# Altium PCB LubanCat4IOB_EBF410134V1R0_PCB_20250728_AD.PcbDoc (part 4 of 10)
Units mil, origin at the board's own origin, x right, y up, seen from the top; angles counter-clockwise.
Board outline 5236.21 x 4055.11 mil, 6 copper layers (TOP, GND02, ART03, PWR04, GND05, BOTTOM), stack 47.2 mil thick; 614 components, 490 nets, 2311 pads, 1916 vias.
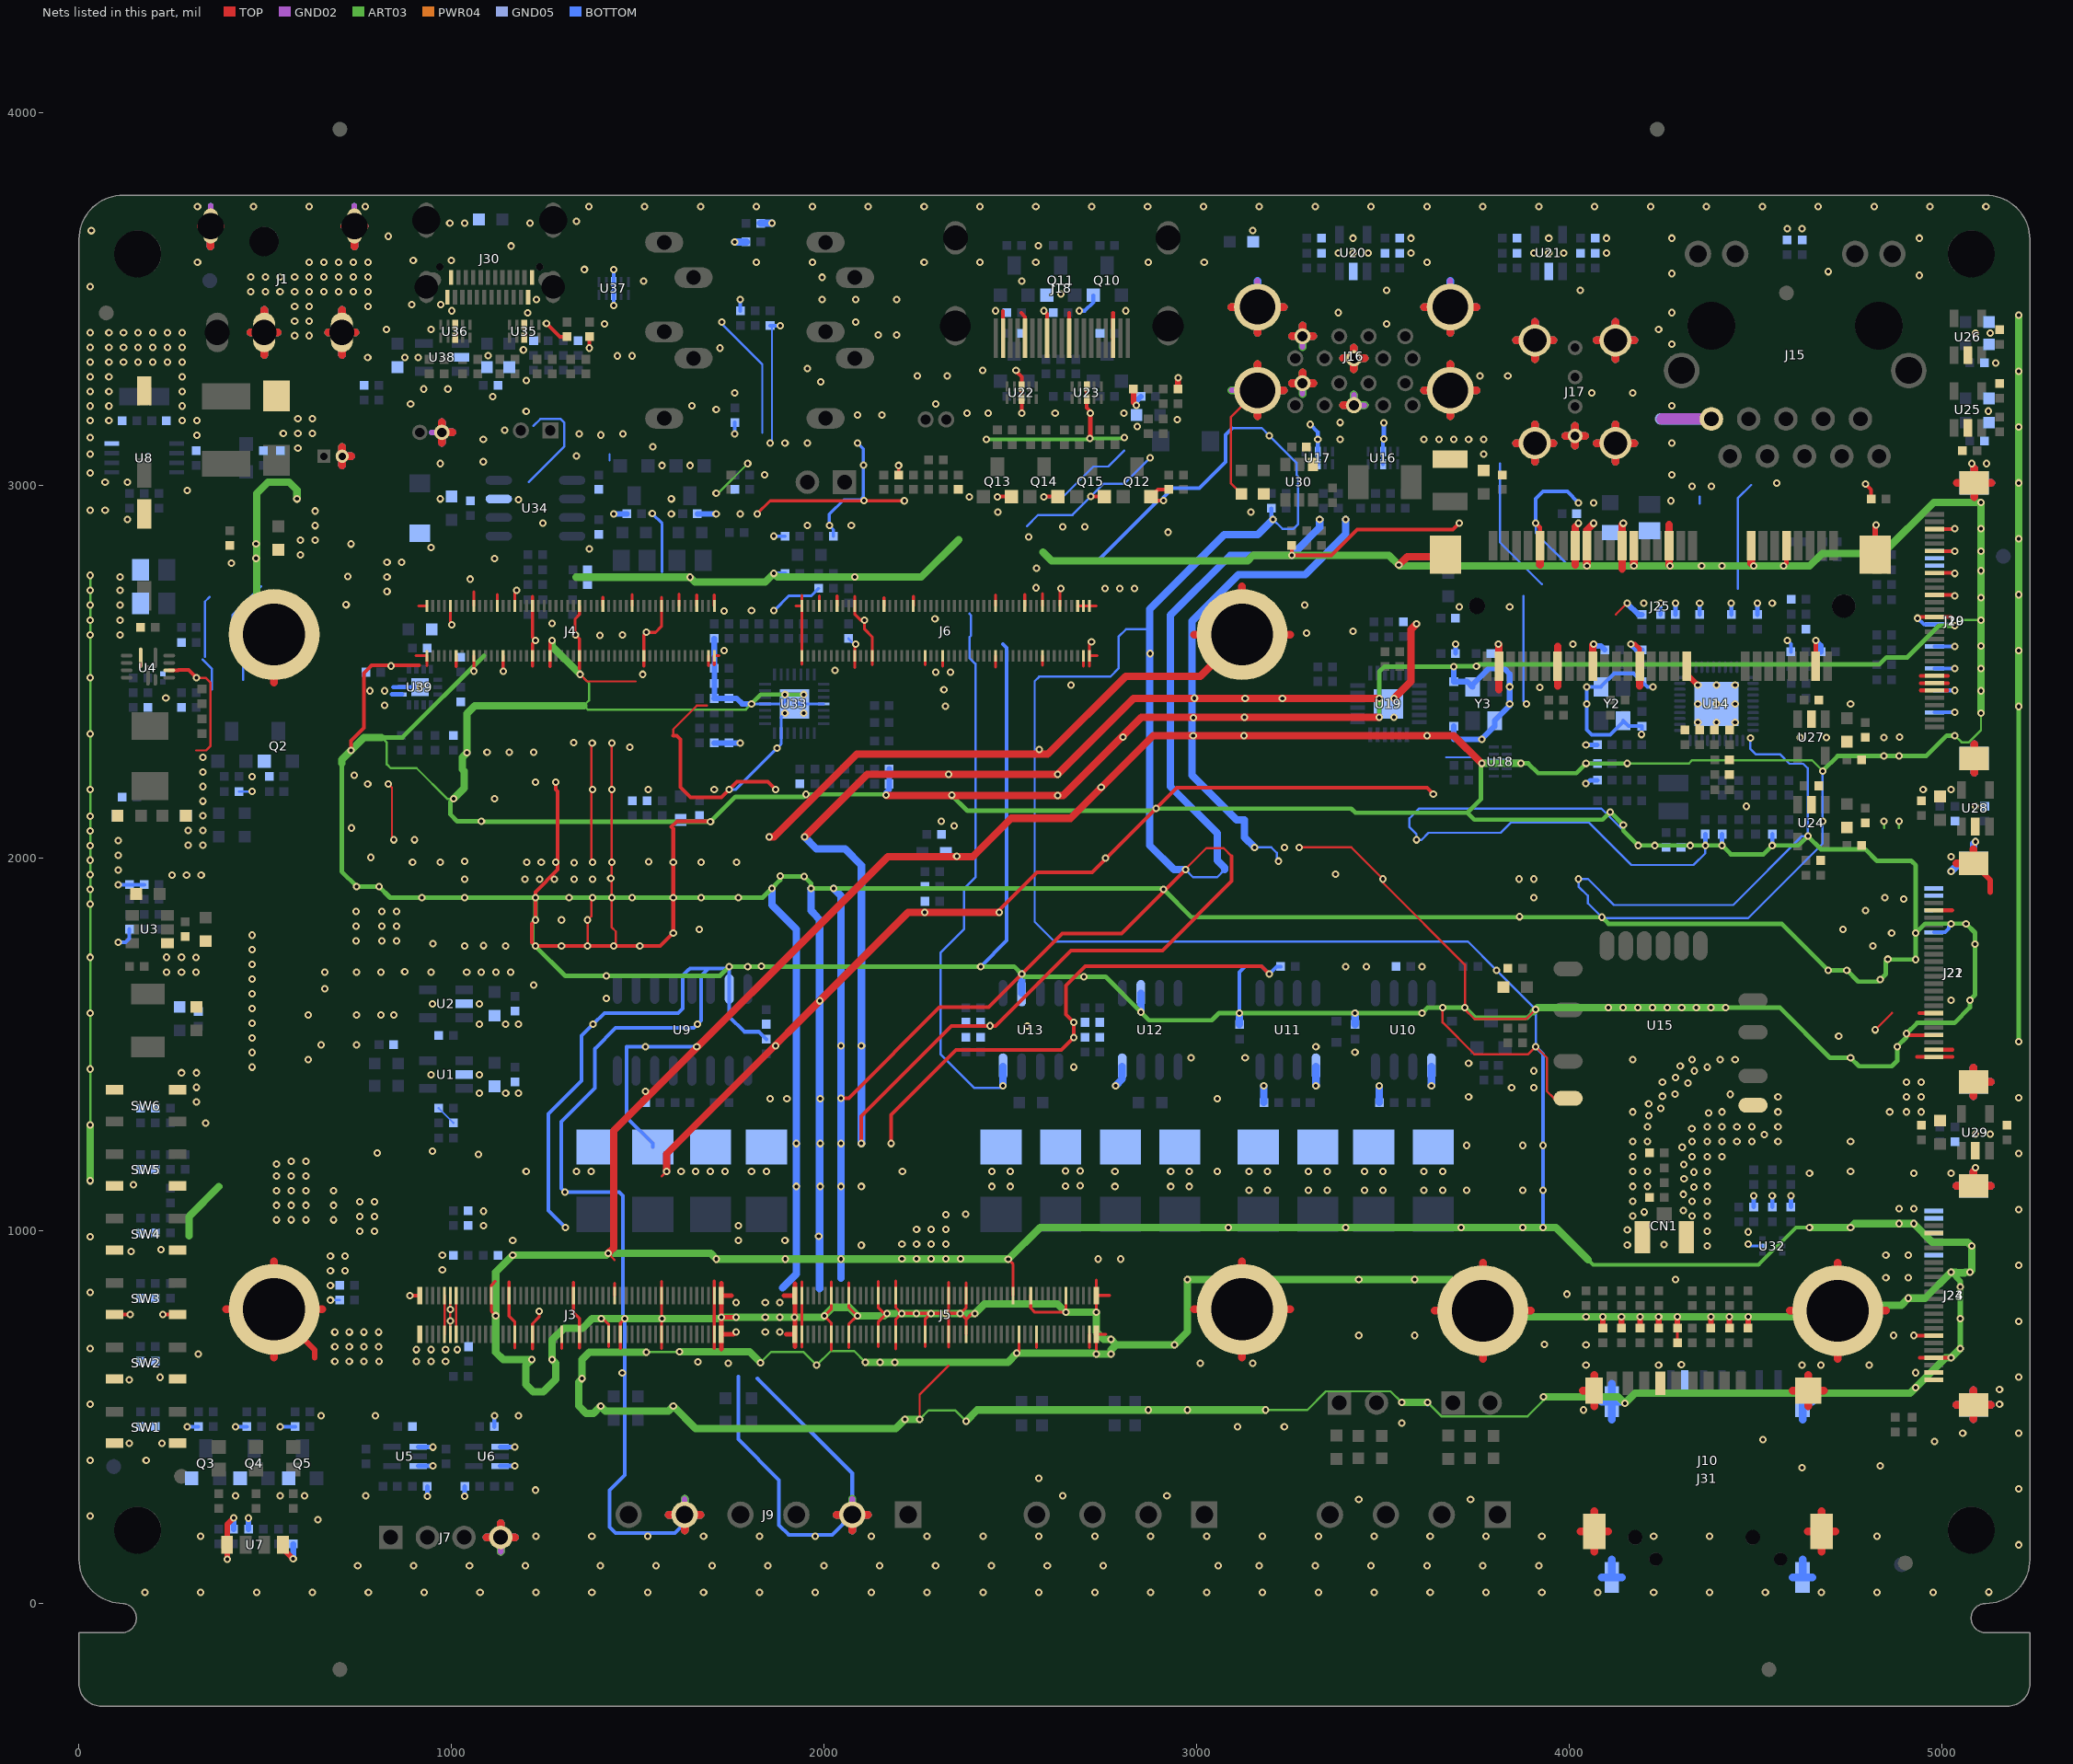
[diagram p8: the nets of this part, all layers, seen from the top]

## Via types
v1: diameter 20, hole 10, TOP to BOTTOM, 1912 vias
v2: diameter 40/50/50/50/50/40 (per signal layer), hole 0, TOP to BOTTOM, 4 vias

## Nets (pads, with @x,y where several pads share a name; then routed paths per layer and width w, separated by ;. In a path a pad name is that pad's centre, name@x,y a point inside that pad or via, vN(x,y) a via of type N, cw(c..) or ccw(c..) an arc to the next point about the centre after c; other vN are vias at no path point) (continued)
GND: C1.2 C2.2 C3.2 C4.2 C5.2 C6.2 C7.2 C8.2 C11.2 C12.2 C13.2 C14.2 C15.2 C16.2 C17.2 C18.1 C19.2 C21.2 C22.2 C23.2 C24.2 C25.2 C26.2 C27.2 C28.2 C29.2 C30.2 C31.2 C32.2 C33.2 C34.2 C35.2 C36.2 C37.2 C38.2 C39.2 C40.2 C41.2 C42.2 C43.2 C44.2 C45.2 C46.2 C47.2 C48.2 C49.2 C50.2 C51.2 C52.2 C53.2 C54.2 C55.2 C58.2 C59.2 C60.2 C61.2 C62.2 C63.2 C64.2 C65.2 C66.2 C67.2 C68.2 C69.2 C70.2 C71.2 C72.2 C73.2 C74.2 C75.2 C76.2 C77.2 C78.2 C79.2 C80.2 C81.2 C82.2 C83.2 C84.2 C85.2 C86.2 C87.2 C88.2 C89.2 C90.2 C92.2 C93.2 C95.2 C96.2 C99.2 C100.2 C101.2 C102.1 C103.2 C104.2 C105.2 C106.2 C107.2 C108.2 C109.2 C110.2 C111.2 C112.2 C124.2 C125.2 C126.2 C127.2 C128.2 C129.2 C130.2 C131.2 C132.2 C133.2 C134.2 C135.2 C136.2 C137.2 C138.2 C139.2 C140.2 C141.2 C142.2 C143.2 C144.2 C147.2 C148.2 C149.2 C150.2 C151.2 C152.2 C153.2 C154.2 C155.2 C158.2 C159.2 C160.2 C161.2 C162.2 C163.2 C164.2 C165.2 C166.2 C167.2 C168.2 C169.2 C170.2 C171.2 C172.2 C173.2 C174.2 C175.2 C180.2 C181.2 C182.2 C183.2 C186.2 C187.2 C188.2 C189.2 C190.2 C192.2 C195.2 C196.2 C203.2 C204.2 C205.2 C206.2 C207.2 C209.2 C210.2 C211.2 C212.2 CN1.2 CN1.3 D1.1 D2.2 D6.1 D7.1 D8.1 D9.1 D10.1 D11.1 D12.1 D13.1 D14.1 D15.1 D16.1 D17.1 D18.1 D20.1 D21.1 D22.1 D24.1 D25.1 D26.1 D27.1 D29.1 D30.1 D31.1 D32.1 D33.1 D34.1 D35.2 D36.2 J1.1 J1.2 J1.3 J1.5 J2.2 J3.7 J3.8 J3.9 J3.10 J3.11 J3.12 J3.23 J3.29 J3.32 J3.38 J3.48 J3.51 J3.54 J3.64 J3.65 J3.68 J3.81 J3.82 J3.99 J3.100 J3.101 J3.102 J3.103 J3.104 J4.1 J4.2 J4.10 J4.11 J4.17 J4.18 J4.26 J4.27 J4.32 J4.37 J4.38 J4.43 J4.53 J4.54 J4.62 J4.72 J4.75 J4.82 J4.88 J4.94 J4.97 J4.99 J4.100 J5.1 J5.2 J5.11 J5.12 J5.17 J5.18 J5.27 J5.28 J5.33 J5.34 J5.44 J5.51 J5.52 J5.57 J5.58 J5.73 J5.76 J5.79 J5.82 J5.91 J5.100 J5.101 J5.102 J5.103 J5.104 J6.1 J6.2 J6.8 J6.14 J6.19 J6.20 J6.25 J6.30 J6.40 J6.43 J6.49 J6.67 J6.68 J6.78 J6.83 J6.84 J6.90 J6.96 J6.97 J6.98 J6.99 J6.100 J7.4 J8.2 J9.2 J9.5 J10.6 J10.10 J10.11 J10.12 J10.13 J15.10 J16.4 J16.7 J16.13 J16.16 J16.19 J16.20 J16.21 J16.22 J17.4 J17.5 J17.6 J17.7 J17.8 J18.2 J18.5 J18.8 J18.11 J18.17 J19.6 J19.7 J19.8 J19.16 J19.19 J19.22 J19.25 J19.28 J19.31 J19.32 J20.6 J20.7 J20.8 J20.16 J20.19 J20.22 J20.25 J20.28 J20.31 J20.32 J21.4 J21.18 J21.21 J21.23 J21.24 J21.25 J21.26 J22.4 J22.18 J22.21 J22.23 J22.24 J22.25 J22.26 J23.4 J23.18 J23.21 J23.23 J23.24 J23.25 J23.26 J24.4 J24.18 J24.21 J24.23 J24.24 J24.25 J24.26 J25.4 J25.9 J25.15 J25.18 J25.21 J25.26 J25.27 J25.29 J25.34 J25.35 J25.37 J25.40 J25.43 J25.50 J25.53 J25.54 J30.A1 J30.A12 J30.B1 J30.B12 J31.5 J31.8 J31.9 J31.10 J31.11 L5.2 L7.2 Q2.2 Q3.2 Q4.2 Q5.2 Q10.2 Q11.2 Q12.2 Q13.2 Q14.2 Q15.2 R4.2 R5.2 R7.2 R9.2 R16.2 R17.1 R20.2 R22.1 R24.2 R40.2 R41.2 R42.2 R64.2 R65.2 R72.2 R73.2 R83.2 R86.2 R91.2 R92.2 R98.2 R99.2 R100.2 R101.2 R102.2 R103.2 R121.2 R125.2 R142.2 R146.2 R157.2 R158.2 R159.2 R160.2 R166.2 R168.2 R174.2 R176.2 R202.2 R211.1 R214.2 R215.1 R217.2 R218.2 R219.2 R228.2 R229.2 R234.1 R235.2 R237.2 SS1.1 SS2.1 SS3.1 SS4.1 SS5.1 SS6.1 SW1.1 SW1.2 SW2.1 SW2.2 SW3.1 SW3.2 SW4.1 SW4.2 SW5.1 SW5.2 SW6.1 SW6.2 U1.2 U2.2 U3.1 U4.2 U4.10 U5.1 U5.3 U6.1 U6.3 U7.1 U7.4 U8.4 U9.15 U10.5 U11.5 U12.2 U12.8 U13.2 U13.8 U14.41 U15.1 U15.5 U16.3 U16.8 U17.3 U17.8 U18.3 U18.8 U19.25 U20.2 U21.2 U22.3 U22.8 U23.3 U23.8 U24.2 U25.2 U26.2 U27.2 U28.2 U29.2 U30.1 U32.2 U33.4 U33.13 U33.18 U33.29 U34.7 U35.3 U35.8 U36.3 U36.8 U37.3 U37.8 U38.2 U39.8 U39.9 U39.15 Y2.2 Y2.4 Y3.2 Y3.4 Z1.1 Z2.1 Z3.2 Z4.2 Z5.1 Z6.1 Z7.1 Z8.1 Z9.1 Z10.1 Z11.1 Z12.1 | length 140963.4
  TOP w6: 315,2289.37 341,2289.37 353,2301.37 353,2471.37 340,2484.37 v1(315,2484.37) ; v1(830,2199.37) 840,2189.37 840,2054.37 v1(845,2049.37) ; v1(900,2049.37) v1@905,2054.37 ; J3.8@980.8,722.26 J3.7@980.8,826.59 ; J3.10@996.55,722.26 v1(996.55,757.88) v1(996.55,789.37) J3.9@996.55,826.59 ; J3.12@1012.29,722.26 J3.11@1012.29,826.59 ; v1@1200,3195.37 v1(1200,3199.37) ; v1(1344.84,2493.74) 1363.84,2474.74 1493.57,2474.74 ; v1(1365,1764.37) v1(1365,1834.37) 1375,1844.37 1375,1890.97 v1(1378.6,1894.57) v1@1375,1898.17 ; v1@1375,1985.77 v1(1378.2,1988.97) 1375,1992.17 1375,2181.77 v1(1378.2,2184.97) 1375,2188.17 1375,2306.17 v1(1377.6,2308.77) ; v1(1420,939.37) 1437.49,921.88 ; v1(1430,2309.37) v1(1430,2184.37) v1(1430,1989.37) v1(1430,1894.37) 1430,1814.35 1440.74,1803.6 1440.74,1770.12 v1(1435,1764.37) ; 1563.48,1146.19 v1(1576.66,1159.37) ; 1595,2329.27 1595,2346.24 1658.13,2409.37 1685,2409.37 ; v1(1645,3214.37) v1@1646,3215.37 ; v1(2256.26,494.37) 2256.26,560.63 2333.86,638.23 ; U23.8@2704.7,3231.85 U23.8@2705,3232.15 ; v1@2730.51,919.88 v1(2735,924.37) ; v1(2970,1969.37) 2970,1971.37 3025.65,2027.02 3072.25,2027.02 3093.95,2005.32 ; C147.2@3120,2977.87 3092,3005.87 3092,3184.77 J16.20@3163.19,3255.96 ; v1(3275,2029.37) 3415,2029.37 v1(3500,1944.37) 3500,1934.37 3720,1714.37 v1(3720,1599.37) 3720,1594.37 3745,1569.37 3885,1569.37 v1(3910,1594.37) ; v1(3660,1599.37) 3660,1559.37 3745,1474.37 3890,1474.37 v1(3910,1494.37) 3940,1464.37 3940,1374.37 3958.78,1355.59 U15.5@3996.97,1355.59 ; 4125,2654.37 v1(4155,2684.37) ; v1(4821,1539.37) 4866.27,1584.64
  TOP w8: 904.75,2543.51 J4.1@933.55,2543.51 933.55,2517.02 ; 911.6,2677.37 J4.2@933.55,2677.37 ; J4.10@996.54,2677.37 996.54,2629.83 v1(1000,2626.37) ; 1012.29,2514.26 J4.11@1012.29,2543.51 ; 1059.53,2513.5 J4.17@1059.53,2543.51 ; J4.18@1059.53,2677.37 1059.53,2715.64 ; 1117,864.57 1106.78,854.35 J3.23@1106.78,826.59 1106.78,783.99 v1(1118.42,772.36) ; J4.26@1122.53,2677.37 1122.53,2707.5 ; J4.27@1138.28,2543.51 1138.28,2502.09 v1(1138.4,2501.97) ; 1154.03,862.6 J3.29@1154.03,826.59 1154.03,770.74 1169.78,754.99 J3.32@1169.78,722.26 1169.78,685.59 ; J4.32@1169.77,2677.37 1169.77,2714.14 v1(1175,2719.37) ; 1217.02,683.15 J3.38@1217.02,722.26 1217.02,750.79 1235,768.77 v1(1235,784.37) ; 1217.02,2515.59 J4.37@1217.02,2543.51 1217.02,2576.39 v1(1225,2584.37) 1217.02,2592.36 J4.38@1217.02,2677.37 1217.02,2702.36 ; 1264.26,2513.91 J4.43@1264.26,2543.51 1264.26,2578.63 v1(1270,2584.37) ; 1295.76,684.73 J3.48@1295.76,722.26 ; 1327.26,861.11 J3.51@1327.26,826.59 1327.26,781.31 1343,765.57 J3.54@1343,722.26 1343,685.77 ; 1343,2508.57 J4.53@1343,2543.51 1343,2589.37 v1(1333,2599.37) 1331.4,2600.97 1331.4,2642.37 1343,2653.97 J4.54@1343,2677.37 ; v1(1402.02,764.37) 1405.74,764.37 1421.74,748.37 J3.64@1421.74,722.26 1421.74,689.83 ; J4.62@1405.99,2677.37 1405.99,2699.78 ; v1(1435,2924.37) v1@1435.16,2924.21 ; J3.65@1437.49,826.59 1437.49,859.08 ; 1453.24,684.41 J3.68@1453.24,722.26 1453.24,752.61 v1(1465,764.37) ; J4.72@1484.73,2677.37 1484.73,2707.64 ; 1516.23,2516 J4.75@1516.23,2543.51 1516.23,2599.6 v1(1523,2606.37) 1547.47,2606.37 1563.47,2622.37 J4.82@1563.47,2677.37 1563.47,2700.84 ; 1563.48,683.89 J3.82@1563.48,722.26 1563.48,763.48 v1(1564.37,764.37) 1563.48,765.26 J3.81@1563.48,826.59 1563.48,864.29 ; J4.88@1610.72,2677.37 1610.72,2708.85 ; J4.94@1657.96,2677.37 1657.96,2706.93 ; 1689.46,2517.11 J4.97@1689.46,2543.51 ; 1705.21,684.56 J3.100@1705.21,722.26 J3.99@1705.21,826.59 1705.21,864.78 ; 1705.2,2519.77 J4.99@1705.2,2543.51 1717.94,2543.51 ; J4.100@1705.2,2677.37 1705.2,2706.57 ; v1(1820,2924.37) 1855,2959.37 v1(2215,2959.37) ; 1924,2677.37 J6.2@1940.15,2677.37 ; 1940.15,688.12 J5.2@1940.15,722.26 J5.1@1940.15,826.59 1940.15,862.73 ; 1940.15,2520.72 J6.1@1940.15,2543.51 J6.2@1940.15,2677.37 ; 1940.15,2705.62 J6.2@1940.15,2677.37 ; J6.8@1987.39,2677.37 1987.39,2704.58 ; 2018.89,681.08 J5.12@2018.89,722.26 2018.89,753.25 v1(2000.59,771.56) 2018.89,789.87 J5.11@2018.89,826.59 2018.89,862.48 ; J6.14@2034.64,2677.37 2034.64,2703.81 ; 2066.14,687.51 J5.18@2066.14,722.26 2066.14,749.91 2087.79,771.56 v1(2089.57,771.56) 2066.14,794.99 J5.17@2066.14,826.59 2066.14,861.03 ; 2081.88,2512.05 J6.19@2081.88,2543.51 2081.88,2571.25 v1(2085,2574.37) ; 2081.88,2702.65 J6.20@2081.88,2677.37 2081.88,2655.37 2097.88,2639.37 v1(2108.26,2639.37) 2108.26,2614.51 2129.13,2593.64 J6.25@2129.13,2543.51 2129.13,2519.64 ; 2144.88,689.29 J5.28@2144.88,722.26 2144.88,754.75 v1(2168.5,778.37) 2160.88,778.37 2144.88,794.37 J5.27@2144.88,826.59 2144.88,863.65 ; J6.30@2160.62,2677.37 2160.62,2699.39 ; 2192.12,682.85 J5.34@2192.12,722.26 2192.12,762.62 v1(2207.87,778.37) ; 2192.12,865.89 J5.33@2192.12,826.59 2192.12,794.12 v1(2207.87,778.37) ; C183.2@2200,3029.05 v1(2200,3054.37) ; J6.40@2239.36,2677.37 2239.36,2703.41 ; 2270.86,689.43 J5.44@2270.86,722.26 2270.86,762.62 v1(2286.61,778.37) ; 2270.86,2519.71 J6.43@2270.86,2543.51 ; 2318.1,2516.07 J6.49@2318.1,2543.51 ; 2333.86,687.63 J5.52@2333.86,722.26 2333.86,770.5 v1(2325.98,778.37) ; 2333.86,861.43 J5.51@2333.86,826.59 2333.86,786.24 v1(2325.98,778.37) ; J5.58@2381.1,722.26 2381.1,762.62 ; 2381.1,860.67 J5.57@2381.1,826.59 2381.1,794.12 v1(2365.35,778.37) ; v1(2404.72,778.37) 2396.85,778.37 2381.1,762.62 ; 2459.84,2513.8 J6.67@2459.84,2543.51 ; J6.68@2459.84,2677.37 2459.84,2706.61 ; v1(2494,923.37) 2507.08,910.29 J5.73@2507.08,826.59 ; v1(2517,671.37) 2522.83,677.2 J5.76@2522.83,722.26 ; J6.78@2538.57,2677.37 2538.57,2707.59 ; J5.79@2554.33,826.59 2554.33,792.87 2565.64,781.55 v1(2648.82,781.55) J5.91@2648.82,826.59 ; 2570.08,686.85 J5.82@2570.08,722.26 ; 2585.82,2518.19 J6.83@2585.82,2543.51 ; J6.84@2585.82,2677.37 2585.82,2710.75 ; J6.90@2633.06,2677.37 2633.06,2721.8 v1(2635.63,2724.37) ; J6.96@2680.31,2677.37 J6.98@2696.06,2677.37 J6.100@2711.8,2677.37 2730.6,2677.37 ; 2696.06,2515.91 J6.97@2696.06,2543.51 ; 2711.81,687.38 J5.100@2711.81,722.26 ; 2711.8,2515.91 J6.99@2711.8,2543.51 ; v1(2717.48,2581.37) 2711.8,2575.69 J6.99@2711.8,2543.51 ; 2730.51,681.86 J5.104@2730.51,722.26 2755.51,722.26 ; v1(2730.51,781.55) J5.103@2730.51,826.59 ; 2730.51,867.28 J5.103@2730.51,826.59 ; 2732.14,2543.51 J6.99@2711.8,2543.51 ; 2766.18,826.59 J5.103@2730.51,826.59 ; C59.2@4290.32,699.37 C58.2@4290.32,739.37 ; v1(2207.87,778.37) v1(2247.24,778.37) v1(2286.61,778.37) ; v1(2286.61,778.37) v1(2325.98,778.37) ; v1(2325.98,778.37) v1(2365.35,778.37) ; v1(2365.35,778.37) 2381.1,762.62
  TOP w10: SW3.2@95.35,775.54 v1(137.52,775.54) ; v1(224.92,775.54) SW3.1@264.65,775.54 ; U4.10@242.09,2504.53 265.3,2504.53 266.3,2505.53 293.84,2505.53 v1(315,2484.37) ; v1(730,2289.37) 730,2315.37 765,2350.37 765,2497.37 785,2517.37 913,2517.37 ; v1(888.22,826.59) J3.101@914.85,826.59 ; v1(1254.31,3435.57) 1290.18,3399.69 D36.2@1310,3399.69 ; v1(1280,2204.37) 1280,2184.37 1285,2179.37 1285,1969.37 1225,1909.37 v1(1225,1894.37) v1(1225,1834.37) 1215,1824.37 1215,1774.37 v1(1225,1764.37) v1(1295,1764.37) v1(1365,1764.37) v1(1435,1764.37) v1(1505,1764.37) 1560,1764.37 v1(1595,1799.37) v1(1595,1894.37) v1(1595,1989.37) 1595,2079.37 1590,2084.37 1605,2099.37 1694,2099.37 v1(1695,2098.37) ; v1(1370,3369.37) D35.2@1370,3399.69 ; 1595,2329.27 1604,2329.27 1614,2319.27 1614,2190.37 1641,2163.37 1724,2163.37 v1(1745,2184.37) 1766,2205.37 1849,2205.37 v1(1870,2184.37) ; v1(2045,1356.37) 2066,1356.37 2310,1600.37 2441,1600.37 v1(2530,1689.37) 2638.65,1798.02 2798.65,1798.02 v1(2970,1969.37) ; v1(2100,1234.37) 2100,1307.37 2342,1549.37 2460,1549.37 2663,1752.37 2908,1752.37 3093.95,1938.32 3093.95,2005.32 ; v1(2180,1234.37) 2180,1311.37 2354.35,1485.72 2636.35,1485.72 v1(2670,1519.37) v1(2670,1559.37) 2649,1580.37 2649,1658.07 2701.3,1710.37 3174,1710.37 v1(3195,1689.37) ; v1(2465,2969.37) 2466.5,2970.87 Q13.2@2502.5,2970.87 ; v1(2470,1854.37) 2470,1860.37 2571.6,1961.97 2719.6,1961.97 v1(2891,2133.37) 2947,2189.37 3618.2,2189.37 v1(3635,2172.57) ; J18.2@2480.31,3395.56 2480.31,3469.06 ; v1(2515,3309.37) 2515,3306.74 2530,3291.74 U22.3@2530,3266.59 U22.8@2530,3232.15 v1(2530,3194.37) ; 2529,3463.37 2539.36,3453.01 J18.5@2539.36,3395.56 ; v1(2590,2969.37) 2591.5,2970.87 Q14.2@2627.5,2970.87 ; v1(2590,3469.37) 2598.42,3460.95 J18.8@2598.42,3395.56 ; J18.11@2657.48,3395.56 2657.48,3463.89 ; U23.3@2705,3266.59 U23.8@2705,3232.15 2705,3209.37 2714.28,3200.09 v1(2714.28,3194.37) ; v1(2716,2970.87) Q15.2@2752.5,2970.87 ; J18.17@2775.59,3395.56 2775.59,3463.96 ; v1(2910.5,2960.37) 2888,2960.37 Q12.2@2877.5,2970.87 2896.32,2989.69 R146.2@2925,2989.69 ; R174.2@3255,2839.69 v1(3255,2812.89) 3361.52,2812.89 3430.37,2881.74 3687.37,2881.74 v1(3705,2899.37) ; v1(4795,3004.37) 4810.32,2989.05 C76.2@4810.32,2964.37 ; v1(4905,1529.37) 4908.78,1525.59 J22.21@4978.61,1525.59 ; v1(4925,719.37) 4925.87,718.5 J24.18@4978.61,718.5 ; 4933.47,1466.53 J22.24@4978.61,1466.53 5028.78,1466.53 ; v1(4935,2644.37) 4938.07,2647.44 J20.16@4980.62,2647.44 5025.44,2647.44 ; 4939.36,1584.64 J22.18@4978.61,1584.64 ; 4940.45,659.45 J24.21@4978.61,659.45 v1(5025,659.45) ; 4942.96,2450.59 J20.6@4980.62,2450.59 5015,2450.59 ; 4942.96,2489.96 J20.8@4980.62,2489.96 5015.96,2489.96 ; 4943.27,2470.27 J20.7@4980.62,2470.27 5016.27,2470.27 ; J22.23@4978.61,1486.22 5028.78,1486.22 ; J20.19@4980.62,2706.49 5032.88,2706.49 v1(5035,2704.37) ; J20.22@4980.62,2765.55 5033.82,2765.55 v1(5035,2764.37) ; J20.25@4980.62,2824.6 5034.77,2824.6 v1(5035,2824.37) ; J20.28@4980.62,2883.66 5034.29,2883.66 v1(5035,2884.37)
  TOP w12: 1723.91,682.48 J3.104@1723.91,722.26 ; 1723.91,859.26 J3.103@1723.91,826.59 ; 1751.78,826.59 J3.103@1723.91,826.59 ; v1(1763.28,728.91) 1756.63,722.26 J3.104@1723.91,722.26 ; v1(1763.28,768.28) v1(1723.91,768.28) ; 1892.38,826.59 J5.101@1921.45,826.59 ; 1898.29,722.26 J5.102@1921.45,722.26 ; 1921.45,688.52 J5.102@1921.45,722.26 ; 1921.45,859.02 J5.101@1921.45,826.59 ; v1(2712.96,3126.37) 2714.28,3127.68 v1(2714.28,3194.37) ; v1(3910,2899.37) 3921.4,2887.97 J25.43@3921.4,2838.58 ; v1(4165,2574.37) 4177.12,2574.37 4189.12,2562.37 J25.26@4189.12,2515.74 ; v1(4575,2784.21) 4575,2784.37 4582.82,2792.19 J25.9@4582.82,2838.58 ; J25.4@4661.56,2515.74 v1(4661.56,2584.37) ; J22.4@4978.61,1860.23 5027.23,1860.23 ; J3.104@1723.91,722.26 v1(1723.91,768.28) ; v1(1723.91,768.28) J3.103@1723.91,826.59 ; J5.102@1921.45,722.26 1921.45,767.59 v1(1920.76,768.28) 1921.45,768.97 J5.101@1921.45,826.59
  TOP w15: v1(397.44,118.86) U7.1@397.44,157.48 397.44,211.81 v1(415,229.37) ; SS2.1@523.46,789.42 632.09,680.8 632.09,659.37 ; U7.4@547.44,157.48 547.44,146.93 v1(575,119.37) ; D32.1@2830.32,3259.37 2830.32,3223.05 v1(2838,3215.37) ; D29.1@2949.68,3259.37 2949.68,3289.05 v1(2950,3289.37) ; D17.1@4090,739.05 v1(4090,769.37) ; D16.1@4140,739.05 v1(4140,769.37) ; D15.1@4190,739.05 v1(4190,769.37) ; D14.1@4240,739.05 v1(4240,769.37) ; v1(4290,769.37) 4290.32,769.05 C58.2@4290.32,739.37 ; J25.18@4315.1,2515.74 4315.1,2494.27 v1(4345,2464.37) ; D13.1@4380,739.05 v1(4380,769.37) ; D12.1@4430,739.05 v1(4430,769.37) ; D11.1@4480,739.05 v1(4480,769.37) ; J25.54@4821.01,2814.95 4821.01,2891.38 v1(4824,2894.37) ; J22.26@5084.99,1986.22 5130,1941.21 5130,1909.37
  TOP w20: v1(1420,939.37) 1434.64,954.01 1434.64,1236.94 1434.64,1268.35 2170.86,2004.57 2398.95,2004.57 2501.74,2107.37 2661,2107.37 2883,2329.37 v1(3127,2329.37) v1(3618.4,2329.37) 3690,2329.37 v1(3765,2254.37) ; v1(1576.66,1159.37) 1576.66,1206.03 2225,1854.37 v1(2270,1854.37) v1(2470,1854.37) ; v1(1852.5,2056.87) 1865.38,2056.87 2087.73,2279.22 2600.05,2279.22 2809.2,2488.37 3009.82,2488.37 SS4.1@3121.89,2600.44 ; v1(1947.5,2056.87) 2115.85,2225.22 v1(2626.41,2225.22) 2830.56,2429.37 v1(3130,2429.37) v1(3230,2429.37) v1(3490,2429.37) ; v1(2166,2169.37) 2166.7,2168.67 v1(2626.6,2168.67) 2641.7,2168.67 2851.5,2378.47 v1(3490,2378.47) ; v1(3529.37,2429.37) 3575,2475 3575,2614.37 v1(3590,2629.37) ; v1(3542.4,2786.77) 3565,2809.37 3661.88,2809.37 J25.53@3667.47,2814.95 ; v1(3810,2574.37) 3811.17,2573.2 J25.50@3811.17,2515.74 3811.17,2452.54 ; 3921.4,2786.97 J25.43@3921.4,2838.58 ; 3968.65,2462.72 J25.40@3968.65,2515.74 3968.65,2569.02 ; 4015.89,2787.26 J25.37@4015.89,2838.58 4015.89,2889.84 ; v1(4047.39,2784.21) J25.35@4047.39,2838.58 4047.39,2881.33 v1(4065,2898.95) ; J25.34@4063.14,2515.74 4063.14,2572.51 v1(4065,2574.37) ; 4141.88,2776.49 J25.29@4141.88,2838.58 4141.88,2895.82 v1(4145,2898.95) ; v1(4173.37,2784.21) J25.27@4173.37,2838.58 ; 4189.12,2462.49 J25.26@4189.12,2515.74 ; 4267.86,2895.23 J25.21@4267.86,2838.58 4267.86,2786.51 v1(4270,2784.37) ; v1@4488.33,2790.88 J25.15@4488.33,2838.58
  TOP w21: 326.66,3696.82 J1.1@353.36,3696.82 ; 353.36,3642.57 J1.1@353.36,3696.82 ; 380.06,3696.82 J1.1@353.36,3696.82 ; 394.41,789.42 SS2.1@523.46,789.42 ; 460.53,3411.32 J1.2@497.06,3411.32 ; 497.06,3351.17 J1.2@497.06,3411.32 ; 497.06,3471.47 J1.2@497.06,3411.32 ; 523.46,660.38 SS2.1@523.46,789.42 ; 523.46,918.47 SS2.1@523.46,789.42 ; 523.46,2471.39 SS1.1@523.46,2600.44 ; 533.59,3411.32 J1.2@497.06,3411.32 ; 652.51,789.42 SS2.1@523.46,789.42 ; 669.13,3411.32 J1.3@705.66,3411.32 ; 705.66,3351.17 J1.3@705.66,3411.32 ; 705.66,3471.47 J1.3@705.66,3411.32 ; 706.26,3054.25 J8.2@706.26,3078.97 ; 706.26,3103.69 J8.2@706.26,3078.97 ; 712.46,3696.82 J1.5@739.16,3696.82 ; 730.98,3078.97 J8.2@706.26,3078.97 ; 739.16,3642.57 J1.5@739.16,3696.82 ; 742.19,3411.32 J1.3@705.66,3411.32 ; 765.87,3696.82 J1.5@739.16,3696.82 ; 974.06,3115.23 J2.2@974.06,3142.9 ; 974.06,3170.57 J2.2@974.06,3142.9 ; 1001.73,3142.9 J2.2@974.06,3142.9 ; 1093.39,177.48 J7.4@1131.89,177.48 ; 1131.89,215.98 J7.4@1131.89,177.48 ; 1170.39,177.48 J7.4@1131.89,177.48 ; 1582.95,238.19 J9.5@1625.39,238.19 ; 1625.39,195.75 J9.5@1625.39,238.19 ; 1667.83,238.19 J9.5@1625.39,238.19 ; 2032.95,238.19 J9.2@2075.39,238.19 ; 2075.39,195.75 J9.2@2075.39,238.19 ; 2117.82,238.19 J9.2@2075.39,238.19 ; 2992.84,789.42 SS3.1@3121.89,789.42 ; 2992.84,2600.44 SS4.1@3121.89,2600.44 ; 3093.19,3479.56 J16.19@3163.19,3479.56 ; 3121.89,660.38 SS3.1@3121.89,789.42 ; 3121.89,918.47 SS3.1@3121.89,789.42 ; 3121.89,2729.49 SS4.1@3121.89,2600.44 ; 3163.19,3185.96 J16.20@3163.19,3255.96 ; 3163.19,3325.96 J16.20@3163.19,3255.96 ; 3163.19,3409.56 J16.19@3163.19,3479.56 ; 3233.19,3255.96 J16.20@3163.19,3255.96 ; 3233.19,3479.56 J16.19@3163.19,3479.56 ; 3250.94,789.42 SS3.1@3121.89,789.42 ; 3250.94,2600.44 SS4.1@3121.89,2600.44 ; 3255.44,3274.86 J16.13@3284.09,3274.86 ; 3255.44,3400.86 J16.4@3284.09,3400.86 ; 3284.09,3303.51 J16.13@3284.09,3274.86 ; 3284.09,3429.51 J16.4@3284.09,3400.86 ; 3312.75,3274.86 J16.13@3284.09,3274.86 ; 3312.75,3400.86 J16.4@3284.09,3400.86 ; 3393.24,3215.76 J16.16@3421.89,3215.76 ; 3393.24,3341.76 J16.7@3421.89,3341.76 ; 3421.89,3313.1 J16.7@3421.89,3341.76 ; 3421.89,3370.42 J16.7@3421.89,3341.76 ; 3450.55,3341.76 J16.7@3421.89,3341.76 ; 3610.59,3255.96 J16.21@3680.59,3255.96 ; 3610.59,3479.56 J16.22@3680.59,3479.56 ; 3638.8,785.48 SS6.1@3767.85,785.48 ; 3680.59,3185.96 J16.21@3680.59,3255.96 ; 3680.59,3325.96 J16.21@3680.59,3255.96 ; 3680.59,3409.56 J16.22@3680.59,3479.56 ; 3750.59,3255.96 J16.21@3680.59,3255.96 ; 3750.59,3479.56 J16.22@3680.59,3479.56 ; 3767.85,656.43 SS6.1@3767.85,785.48 ; 3767.85,914.53 SS6.1@3767.85,785.48 ; 3857.12,3114.17 J17.8@3907.43,3114.17 ; 3857.12,3389.76 J17.7@3907.43,3389.76 ; 3896.9,785.48 SS6.1@3767.85,785.48 ; 3907.43,3063.86 J17.8@3907.43,3114.17 ; 3907.43,3164.47 J17.8@3907.43,3114.17 ; 3907.43,3339.45 J17.7@3907.43,3389.76 ; 3907.43,3440.07 J17.7@3907.43,3389.76 ; 3957.74,3114.17 J17.8@3907.43,3114.17 ; 3957.74,3389.76 J17.7@3907.43,3389.76 ; 3989.05,3133.69 J17.4@4015.74,3133.69 ; 4015.74,3107.01 J17.4@4015.74,3133.69 ; 4015.74,3160.38 J17.4@4015.74,3133.69 ; 4029.91,193.1 J10.11@4066.92,193.1 ; 4036.3,571.06 J10.10@4066.92,571.06 ; 4042.43,3133.69 J17.4@4015.74,3133.69 ; 4066.92,138.6 J10.11@4066.92,193.1 ; 4066.92,247.6 J10.11@4066.92,193.1 ; 4066.92,529.05 J10.10@4066.92,571.06 ; 4066.92,613.06 J10.10@4066.92,571.06 ; 4073.66,3114.17 J17.5@4123.97,3114.17 ; 4073.66,3389.76 J17.6@4123.97,3389.76 ; 4103.92,193.1 J10.11@4066.92,193.1 ; 4123.97,3063.86 J17.5@4123.97,3114.17 ; 4123.97,3164.47 J17.5@4123.97,3114.17 ; 4123.97,3339.45 J17.6@4123.97,3389.76 ; 4123.97,3440.07 J17.6@4123.97,3389.76 ; 4174.28,3114.17 J17.5@4123.97,3114.17 ; 4174.28,3389.76 J17.6@4123.97,3389.76 ; 4591.56,785.48 SS5.1@4720.61,785.48 ; 4599.71,571.06 J10.13@4641.72,571.06 ; 4640.15,193.1 J10.12@4677.16,193.1 ; 4641.72,529.05 J10.13@4641.72,571.06 ; 4641.72,613.06 J10.13@4641.72,571.06 ; 4677.16,138.6 J10.12@4677.16,193.1 ; 4677.16,247.6 J10.12@4677.16,193.1 ; 4683.72,571.06 J10.13@4641.72,571.06 ; 4714.16,193.1 J10.12@4677.16,193.1 ; 4720.61,656.43 SS5.1@4720.61,785.48 ; 4720.61,914.53 SS5.1@4720.61,785.48 ; 4849.66,785.48 SS5.1@4720.61,785.48 ; 5038.62,533.46 J24.25@5084.99,533.46 ; 5038.62,1120.08 J24.26@5084.99,1120.08 ; 5038.62,1986.22 J22.26@5084.99,1986.22 5084.99,2024.71 ; 5040.55,3007.67 J20.31@5086.92,3007.67 ; 5084.99,494.97 J24.25@5084.99,533.46 ; 5084.99,571.96 J24.25@5084.99,533.46 ; 5084.99,1158.57 J24.26@5084.99,1120.08 ; 5084.99,1361.11 J22.25@5084.99,1399.6 ; 5084.99,1438.1 J22.25@5084.99,1399.6 ; 5086.92,2229.02 J20.32@5086.92,2267.51 5086.92,2306.01 ; 5086.92,2969.18 J20.31@5086.92,3007.67 ; 5086.92,3046.17 J20.31@5086.92,3007.67 ; 5131.36,533.46 J24.25@5084.99,533.46 ; 5131.36,1120.08 J24.26@5084.99,1120.08 ; 5131.36,1399.6 J22.25@5084.99,1399.6 ; 5133.29,3007.67 J20.31@5086.92,3007.67
  GND02 w15: 326.66,3696.82 J1.1@353.36,3696.82 ; 353.36,3642.57 J1.1@353.36,3696.82 ; 353.36,3751.07 J1.1@353.36,3696.82 ; 380.06,3696.82 J1.1@353.36,3696.82 ; 414.1,789.42 SS2.1@523.46,789.42 ; 414.1,2600.44 SS1.1@523.46,2600.44 ; 460.53,3411.32 J1.2@497.06,3411.32 ; 497.06,3351.17 J1.2@497.06,3411.32 ; 497.06,3471.47 J1.2@497.06,3411.32 ; 523.46,680.06 SS2.1@523.46,789.42 ; 523.46,898.79 SS2.1@523.46,789.42 ; 523.46,2491.08 SS1.1@523.46,2600.44 ; 523.46,2709.81 SS1.1@523.46,2600.44 ; 533.59,3411.32 J1.2@497.06,3411.32 ; 632.82,789.42 SS2.1@523.46,789.42 ; 632.82,2600.44 SS1.1@523.46,2600.44 ; 669.13,3411.32 J1.3@705.66,3411.32 ; 705.66,3351.17 J1.3@705.66,3411.32 ; 705.66,3471.47 J1.3@705.66,3411.32 ; 706.26,3054.25 J8.2@706.26,3078.97 ; 706.26,3103.69 J8.2@706.26,3078.97 ; 712.46,3696.82 J1.5@739.16,3696.82 ; 730.98,3078.97 J8.2@706.26,3078.97 ; 739.16,3642.57 J1.5@739.16,3696.82 ; 739.16,3751.07 J1.5@739.16,3696.82 ; 742.19,3411.32 J1.3@705.66,3411.32 ; 765.87,3696.82 J1.5@739.16,3696.82 ; 946.39,3142.9 J2.2@974.06,3142.9 ; 974.06,3115.23 J2.2@974.06,3142.9 ; 974.06,3170.57 J2.2@974.06,3142.9 ; 1001.73,3142.9 J2.2@974.06,3142.9 ; 1093.39,177.48 J7.4@1131.89,177.48 ; 1131.89,138.98 J7.4@1131.89,177.48 ; 1131.89,215.98 J7.4@1131.89,177.48 ; 1170.39,177.48 J7.4@1131.89,177.48 ; 1582.95,238.19 J9.5@1625.39,238.19 ; 1625.39,195.75 J9.5@1625.39,238.19 ; 1625.39,280.62 J9.5@1625.39,238.19 ; 1667.83,238.19 J9.5@1625.39,238.19 ; 2032.95,238.19 J9.2@2075.39,238.19 ; 2075.39,195.75 J9.2@2075.39,238.19 ; 2075.39,280.62 J9.2@2075.39,238.19 ; 2117.82,238.19 J9.2@2075.39,238.19 ; 3012.53,789.42 SS3.1@3121.89,789.42 ; 3012.53,2600.44 SS4.1@3121.89,2600.44 ; 3093.19,3255.96 J16.20@3163.19,3255.96 ; 3093.19,3479.56 J16.19@3163.19,3479.56 ; 3121.89,680.06 SS3.1@3121.89,789.42 ; 3121.89,898.79 SS3.1@3121.89,789.42 ; 3121.89,2491.08 SS4.1@3121.89,2600.44 ; 3121.89,2709.81 SS4.1@3121.89,2600.44 ; 3163.19,3185.96 J16.20@3163.19,3255.96 ; 3163.19,3325.96 J16.20@3163.19,3255.96 ; 3163.19,3409.56 J16.19@3163.19,3479.56 ; 3163.19,3549.56 J16.19@3163.19,3479.56 ; 3231.25,789.42 SS3.1@3121.89,789.42 ; 3231.25,2600.44 SS4.1@3121.89,2600.44 ; 3233.19,3255.96 J16.20@3163.19,3255.96 ; 3233.19,3479.56 J16.19@3163.19,3479.56 ; 3255.44,3274.86 J16.13@3284.09,3274.86 ; 3255.44,3400.86 J16.4@3284.09,3400.86 ; 3284.09,3246.2 J16.13@3284.09,3274.86 ; 3284.09,3303.51 J16.13@3284.09,3274.86 ; 3284.09,3372.2 J16.4@3284.09,3400.86 ; 3284.09,3429.51 J16.4@3284.09,3400.86 ; 3312.75,3274.86 J16.13@3284.09,3274.86 ; 3312.75,3400.86 J16.4@3284.09,3400.86 ; 3393.24,3215.76 J16.16@3421.89,3215.76 ; 3393.24,3341.76 J16.7@3421.89,3341.76 ; 3421.89,3244.42 J16.16@3421.89,3215.76 ; 3421.89,3313.1 J16.7@3421.89,3341.76 ; 3421.89,3370.42 J16.7@3421.89,3341.76 ; 3450.55,3215.76 J16.16@3421.89,3215.76 ; 3450.55,3341.76 J16.7@3421.89,3341.76 ; 3610.59,3255.96 J16.21@3680.59,3255.96 ; 3610.59,3479.56 J16.22@3680.59,3479.56 ; 3658.48,785.48 SS6.1@3767.85,785.48 ; 3680.59,3185.96 J16.21@3680.59,3255.96 ; 3680.59,3325.96 J16.21@3680.59,3255.96 ; 3680.59,3409.56 J16.22@3680.59,3479.56 ; 3680.59,3549.56 J16.22@3680.59,3479.56 ; 3750.59,3255.96 J16.21@3680.59,3255.96 ; 3750.59,3479.56 J16.22@3680.59,3479.56 ; 3767.85,676.12 SS6.1@3767.85,785.48 ; 3767.85,894.85 SS6.1@3767.85,785.48 ; 3857.12,3114.17 J17.8@3907.43,3114.17 ; 3857.12,3389.76 J17.7@3907.43,3389.76 ; 3877.21,785.48 SS6.1@3767.85,785.48 ; 3907.43,3063.86 J17.8@3907.43,3114.17 ; 3907.43,3164.47 J17.8@3907.43,3114.17 ; 3907.43,3339.45 J17.7@3907.43,3389.76 ; 3907.43,3440.07 J17.7@3907.43,3389.76 ; 3957.74,3114.17 J17.8@3907.43,3114.17 ; 3957.74,3389.76 J17.7@3907.43,3389.76 ; 3989.05,3133.69 J17.4@4015.74,3133.69 ; 4015.74,3107.01 J17.4@4015.74,3133.69 ; 4015.74,3160.38 J17.4@4015.74,3133.69 ; 4042.43,3133.69 J17.4@4015.74,3133.69 ; 4073.66,3114.17 J17.5@4123.97,3114.17 ; 4073.66,3389.76 J17.6@4123.97,3389.76 ; 4123.97,3063.86 J17.5@4123.97,3114.17 ; 4123.97,3164.47 J17.5@4123.97,3114.17 ; 4123.97,3339.45 J17.6@4123.97,3389.76 ; 4123.97,3440.07 J17.6@4123.97,3389.76 ; 4174.28,3114.17 J17.5@4123.97,3114.17 ; 4174.28,3389.76 J17.6@4123.97,3389.76 ; 4611.24,785.48 SS5.1@4720.61,785.48 ; 4720.61,676.12 SS5.1@4720.61,785.48 ; 4720.61,894.85 SS5.1@4720.61,785.48 ; 4829.97,785.48 SS5.1@4720.61,785.48
  GND02 w30: 4249.76,3179.13 J15.10@4381.49,3179.13
  ART03 w6: v1(30,1284.33) v1(30,1434.33) v1(30,1584.33) v1(30,1734.33) v1(30,1876.85) v1(30,1916.21) v1(30,1955.59) v1(30,1994.95) v1(30,2034.33) v1(30,2073.7) v1(30,2113.07) v1(30,2184.32) v1(30,2334.32) v1(30,2484.32) v1(30,2599.32) v1(30,2639.32) v1(30,2679.32) v1(30,2719.32) v1(30,2759.32) ; 812,2324.37 826.2,2310.17 826.2,2252.17 836.6,2241.77 906,2241.77 988.4,2159.37 v1(1005,2159.37) ; v1(1344.84,2493.74) 1369.2,2469.38 1369.2,2423.77 1355,2409.57 1365.4,2399.17 1789.8,2399.17 v1(1805,2414.37) ; v1(1523,674.37) 1524,675.37 v1(1612,675.37) ; v1(1710,2979.37) 1715,2979.37 v1(1795,3059.37) ; v1(1829,646.37) 1858,675.37 1944,675.37 v1(1980,639.37) 2018,677.37 2081,677.37 v1(2111,647.37) ; v1(2256.26,494.37) 2280.26,518.37 2351.63,518.37 v1(2380.63,489.37) ; v1@2802.72,3126.37 v1(2805.72,3129.37) ; v1(3185,519.37) 3297,519.37 3347,569.37 3520,569.37 v1(3550,539.37) ; v1(3620,539.37) 3657,502.37 3888,502.37 3931,545.37 v1(3931,554.37) ; v1(4155,2254.37) 4321.2,2254.37 4330,2263.17 4651.2,2263.17 v1(4680,2234.37) ; 4845,2081.37 v1(4845,2099.37) ; 4885,2081.37 v1(4885,2099.37) ; v1(5035,2329.37) 5053,2311.37 5073,2311.37 5105,2343.37 v1(5105,2389.37) ; v1(5035,2624.37) 5050,2639.37 v1(5105,2639.37)
  ART03 w10: v1(2435,3124.37) 2709.28,3124.37 2711.28,3126.37 v1(2712.96,3126.37) v1@2802.72,3126.37 ; 4050.4,922.77 4064.6,908.57 4508,908.57 4608.8,1009.37 v1(4645,1009.37)
  ART03 w12: 705,2255.37 705,1964.37 v1(745,1924.37) v1(805,1924.37) 835,1894.37 v1(920,1894.37) v1(1035,1894.37) v1(1225,1894.37) ; 812,2324.37 868,2324.37 1087.51,2543.88 ; v1(1005,2159.37) 996.97,2151.34 996.97,2117.4 1015,2099.37 v1(1080,2099.37) 1081,2098.37 v1(1695,2098.37) 1761.8,2165.17 1945,2165.17 v1(1951.4,2171.57) 2163.8,2171.57 v1(2166,2169.37) 2342.4,2169.37 v1(2342.6,2169.17) 2384,2127.77 2885.4,2127.77 v1(2891,2133.37) 3414.6,2133.37 3426,2121.97 3726.6,2121.97 ; v1(1805,2414.37) 1830,2439.37 v1(1895,2439.37) v1(1945,2439.37) ; v1(2991,2377.37) 2992,2378.37 v1(3127.6,2378.37) 3127.7,2378.47 v1(3490,2378.47) v1(3490,2429.37) 3490,2500.77 3503.6,2514.37 v1(3690,2514.37) 3691,2515.37 v1(3751,2515.37) 3756.2,2520.57 4832.8,2520.57 4851.4,2539.17 4907.6,2539.17 4992.8,2624.37 v1(5035,2624.37) ; v1(3765,2254.37) 3762.4,2251.77 3762.4,2157.77 3726.6,2121.97 ; v1(3870,2254.64) 3889.72,2254.64 3916.2,2228.17 4018.8,2228.17 v1(4045,2254.37) v1(4155,2254.37) ; v1@3903.4,1587.77 3888,1572.37 3747,1572.37 v1(3720,1599.37) v1(3660,1599.37) 3620,1599.37 v1(3605,1584.37) v1(3425,1584.37) v1(3115,1584.37) 3059.6,1584.37 3040.4,1565.17 2872.19,1565.17 v1(2850,1587.36) 2755.39,1681.97 v1(2697,1681.97) 2537.4,1681.97 v1(2530,1689.37) 2510,1709.37 v1(2420,1709.37) v1(1795,1709.37) v1(1745.2,1709.37) 1720.2,1684.37 v1(1415,1684.37) 1305,1684.37 v1(1225,1764.37) 1216.4,1772.97 1216.4,1825.77 v1(1225,1834.37) v1(1225,1894.37) ; v1(4419.96,1598.77) 4565.6,1598.77 4700,1464.37 v1(4755,1464.37) 4777.8,1441.57 4865.6,1441.57 4880,1455.97 v1(4880,1494.37) 4905,1519.37 v1(4905,1529.37) 4933.8,1558.17 5033.6,1558.17 5075,1599.57 v1(5075,1619.37) 5089,1633.37 v1(5089,1769.37) 5089,1800.37 v1(5065,1824.37) v1(5025,1824.37) 4955,1824.37 v1(4930,1799.37) ; v1(4680,2234.37) 4720,2274.37 v1(4845,2274.37) v1(4885,2274.37) 4958,2274.37 5013,2329.37 v1(5035,2329.37) ; v1(5206.21,1507.42) v1(5206.21,2407.42) ; v1(1225,1894.37) v1(1315,1894.37) 1315.2,1894.57 v1(1378.6,1894.57) 1378.8,1894.37 v1(1430,1894.37) v1(1485,1894.37) v1(1595,1894.37) v1(1670,1894.37) v1(1770,1894.37) 1835,1894.37 v1(1860,1919.37) 1882,1941.37 v1(1882,1952.37) 1883,1951.37 v1(1946,1951.37) 1965,1932.37 v1(1965,1919.37) v1(2025,1919.37) 2908.4,1919.37 v1(2911.2,1916.57) 2985.9,1841.87 3864.9,1841.87 v1(3866.2,1843.17) 3867.5,1841.87 v1(4087.5,1841.87) 4105.2,1824.17 4570.2,1824.17 v1(4695,1699.37) v1(4745,1699.37) 4775.4,1668.97 4829.6,1668.97 v1(4835,1674.37) 4849.4,1688.77 4849.4,1723.77 v1(4855,1729.37) 4856.1,1728.27 v1(4930,1728.27) v1(4930,1799.37) ; 3726.6,2121.97 3745,2103.57 4089.2,2103.57 v1(4110,2124.37) v1(4145,2089.37) 4145,2074.37 v1(4185,2034.37) v1(4230,2034.37) v1(4325,2034.37) v1(4365,2034.37) v1(4410,2034.37) 4433.6,2010.77 4521.4,2010.77 v1(4545,2034.37) 4615.4,2034.37 v1(4640.4,2059.37) 4675.4,2024.37 4794.4,2024.37 4825.6,1993.17 4918,1993.17 4930,1981.17 v1(4930,1799.37)
  ART03 w15: v1(5025,889.37) 5050,864.37 v1(5050,849.37) v1(5050,764.37) v1(5050,684.37)
  ART03 w20: v1(30,1134.33) v1(30,1284.33) ; 295,986.37 295,1038.37 375,1118.37 ; SS1.1@523.46,2600.44 477,2646.9 477,2979.11 507.26,3009.37 563.83,3009.37 585,2988.2 v1(585,2964.37) ; 705,2255.37 705,2264.37 v1(730,2289.37) 765,2324.37 812,2324.37 ; v1(1005,2159.37) 1034.2,2188.57 1034.2,2233.4 1029,2238.6 1029,2271.37 v1(1041,2283.37) 1041,2388.17 1062.4,2409.57 1355,2409.57 ; v1(1270,2584.37) 1270,2568.58 v1(1344.84,2493.74) ; 1334.2,2754.37 v1(1640,2754.37) 1653,2741.37 1842,2741.37 v1(1865,2764.37) 1874.48,2754.89 v1(2081.88,2754.89) 2260.6,2754.89 2361.08,2855.37 ; v1(1523,674.37) 1370,674.37 1350,654.37 v1(1350,603.37) 1341,594.37 1341,530.37 1361.26,510.11 1380.74,510.11 v1(1400,529.37) 1413,516.37 1582,516.37 v1(1595,529.37) 1655,469.37 2191.89,469.37 v1(2216.89,494.37) v1(2256.26,494.37) ; v1(1612,675.37) 1800,675.37 v1(1829,646.37) ; v1(2111,647.37) v1(2150.37,647.37) v1(2189.74,647.37) 2493,647.37 v1(2517,671.37) 2728.51,671.37 v1(2730.51,669.37) v1(2769.88,669.37) 2769.88,680 2784.25,694.37 ; v1(2380.63,489.37) 2410.63,519.37 v1(2870,519.37) v1(2975,519.37) v1(3185,519.37) ; 2587,2822 2610.38,2798.62 3136.77,2798.62 3151.04,2812.89 v1(3255,2812.89) 3516.28,2812.89 v1(3542.4,2786.77) 3544.96,2784.21 v1(4047.39,2784.21) v1(4173.37,2784.21) 4269.84,2784.21 v1(4270,2784.37) v1(4355,2784.37) v1(4410,2784.37) 4494.84,2784.37 v1(4495,2784.21) v1(4575,2784.21) 4645.15,2784.21 4678.77,2817.82 4840.99,2817.82 4978.54,2955.37 v1(5105,2955.37) v1(5105,2884.37) v1(5105,2824.37) v1(5105,2771.64) v1(5105,2699.37) v1(5105,2639.37) v1(5105,2569.37) v1(5105,2509.37) v1(5105,2449.37) v1(5105,2389.37) ; v1(3550,539.37) v1(3620,539.37) ; v1(3765,2254.37) 3765.28,2254.64 v1(3870,2254.64) ; v1@3903.4,1587.77 v1(3910,1594.37) 3914.4,1598.77 v1(4105,1598.77) v1(4144.37,1598.77) v1(4183.74,1598.77) v1(4223.11,1598.77) v1(4262.48,1598.77) v1(4301.85,1598.77) v1(4341.22,1598.77) v1(4380.59,1598.77) v1(4419.96,1598.77) ; v1(3931,554.37) 4131.34,554.37 v1(4148.85,536.86) 4176.36,564.37 4915,564.37 v1(4930,579.37) 5010.08,659.45 v1(5025,659.45) 5049.92,684.37 v1(5050,684.37) ; 4050.4,922.77 3963.8,1009.37 v1(3930,1009.37) v1(3875,1009.37) v1(3710,1009.37) v1(3400,1009.37) v1(3085,1009.37) 2580,1009.37 v1(2494,923.37) 2493,924.37 v1(2045,924.37) v1(1895.8,924.37) v1(1710.75,924.37) 1695.75,939.37 v1(1420,939.37) 1415.31,934.68 v1(1164.06,934.68) 1118.42,889.04 v1(1118.42,772.36) 1118.42,674.37 1138.42,654.37 v1(1215,654.37) 1199.6,638.97 1199.6,587.85 1219.2,568.25 1246.55,568.25 1279.64,601.35 1279.64,644.73 v1(1270,654.37) 1270,707.17 1301.6,738.77 1351.82,738.77 1377.42,764.37 v1(1402.02,764.37) v1(1465,764.37) v1(1564.37,764.37) 1720,764.37 v1(1723.91,768.28) v1(1763.28,768.28) v1(1842.02,768.28) v1(1881.39,768.28) v1(1920.76,768.28) 1997.31,768.28 v1(2000.59,771.56) 2000.59,772.6 2022.55,794.56 2067.61,794.56 2089.57,772.6 v1(2089.57,771.56) 2161.69,771.56 v1(2168.5,778.37) v1(2207.87,778.37) v1(2247.24,778.37) v1(2286.61,778.37) v1(2325.98,778.37) v1(2365.35,778.37) v1(2404.72,778.37) 2430.72,804.37 2626,804.37 v1(2648.82,781.55) v1(2730.51,781.55) 2730.51,728.74 2750.51,708.74 v1(2769.88,708.74) 2784.25,694.37 ; v1(4645,1009.37) v1(4755,1009.37) 4765,1019.37 v1(4885,1019.37) v1(4925,1019.37) 4974.6,969.77 5069,969.77 5079.4,959.37 v1(5080,959.37) 5080,894.37 v1(5075,889.37) 5062.77,889.37 5060.77,887.37 5039.23,887.37 5037.23,889.37 v1(5025,889.37) 4955,819.37 v1(4910,819.37) 4891,800.37 4735.49,800.37 SS5.1@4720.61,785.48 4704.49,769.37 v1(4480,769.37) v1(4430,769.37) v1(4380,769.37) v1(4290,769.37) v1(4240,769.37) v1(4190,769.37) v1(4140,769.37) v1(4090,769.37) v1(4045,769.37) 3783.96,769.37 SS6.1@3767.85,785.48 3683.96,869.37 v1(3585,869.37) v1(3435,869.37) 3201.84,869.37 SS3.1@3121.89,789.42 3041.94,869.37 v1(2975,869.37) 2975,729.37 v1(2940,694.37) 2784.25,694.37 ; v1(5206.21,2407.42) v1(5206.21,2557.42) v1(5206.21,2707.42) v1(5206.21,2857.42) v1(5206.21,3007.42) v1(5206.21,3157.42) v1(5206.21,3307.42) v1(5206.21,3457.42)
  ART03 w21: 326.66,3696.82 J1.1@353.36,3696.82 ; 353.36,3642.57 J1.1@353.36,3696.82 ; 380.06,3696.82 J1.1@353.36,3696.82 ; 460.53,3411.32 J1.2@497.06,3411.32 ; 497.06,3351.17 J1.2@497.06,3411.32 ; 497.06,3471.47 J1.2@497.06,3411.32 ; 523.46,680.06 SS2.1@523.46,789.42 ; 523.46,898.79 SS2.1@523.46,789.42 ; 523.46,2491.08 SS1.1@523.46,2600.44 ; 523.46,2709.81 SS1.1@523.46,2600.44 ; 533.59,3411.32 J1.2@497.06,3411.32 ; 632.82,789.42 SS2.1@523.46,789.42 ; 632.82,2600.44 SS1.1@523.46,2600.44 ; 669.13,3411.32 J1.3@705.66,3411.32 ; 705.66,3471.47 J1.3@705.66,3411.32 ; J8.2@706.26,3078.97 706.26,3103.69 ; 712.46,3696.82 J1.5@739.16,3696.82 ; 739.16,3642.57 J1.5@739.16,3696.82 ; 742.19,3411.32 J1.3@705.66,3411.32 ; 765.87,3696.82 J1.5@739.16,3696.82 ; 1093.39,177.48 J7.4@1131.89,177.48 ; 1131.89,138.98 J7.4@1131.89,177.48 ; 1131.89,215.98 J7.4@1131.89,177.48 ; 1170.39,177.48 J7.4@1131.89,177.48 ; 1582.95,238.19 J9.5@1625.39,238.19 ; 1625.39,195.75 J9.5@1625.39,238.19 ; 1625.39,280.62 J9.5@1625.39,238.19 ; 1667.83,238.19 J9.5@1625.39,238.19 ; 2032.95,238.19 J9.2@2075.39,238.19 ; 2075.39,195.75 J9.2@2075.39,238.19 ; 2075.39,280.62 J9.2@2075.39,238.19 ; 2117.82,238.19 J9.2@2075.39,238.19 ; 3093.19,3255.96 J16.20@3163.19,3255.96 ; 3093.19,3479.56 J16.19@3163.19,3479.56 ; 3163.19,3185.96 J16.20@3163.19,3255.96 ; 3163.19,3325.96 J16.20@3163.19,3255.96 ; 3163.19,3409.56 J16.19@3163.19,3479.56 ; 3233.19,3255.96 J16.20@3163.19,3255.96 ; 3233.19,3479.56 J16.19@3163.19,3479.56 ; 3255.44,3274.86 J16.13@3284.09,3274.86 ; 3255.44,3400.86 J16.4@3284.09,3400.86 ; 3284.09,3246.2 J16.13@3284.09,3274.86 ; 3284.09,3303.51 J16.13@3284.09,3274.86 ; 3284.09,3372.2 J16.4@3284.09,3400.86 ; 3284.09,3429.51 J16.4@3284.09,3400.86 ; 3312.75,3274.86 J16.13@3284.09,3274.86 ; 3312.75,3400.86 J16.4@3284.09,3400.86 ; 3393.24,3215.76 J16.16@3421.89,3215.76 ; 3393.24,3341.76 J16.7@3421.89,3341.76 ; 3421.89,3244.42 J16.16@3421.89,3215.76 ; 3421.89,3313.1 J16.7@3421.89,3341.76 ; 3421.89,3370.42 J16.7@3421.89,3341.76 ; 3450.55,3215.76 J16.16@3421.89,3215.76 ; 3450.55,3341.76 J16.7@3421.89,3341.76 ; 3610.59,3255.96 J16.21@3680.59,3255.96 ; 3610.59,3479.56 J16.22@3680.59,3479.56 3680.59,3409.56 ; 3680.59,3185.96 J16.21@3680.59,3255.96 ; 3680.59,3325.96 J16.21@3680.59,3255.96 ; 3750.59,3255.96 J16.21@3680.59,3255.96 ; 3857.12,3114.17 J17.8@3907.43,3114.17 ; 3857.12,3389.76 J17.7@3907.43,3389.76 ; 3907.43,3063.86 J17.8@3907.43,3114.17 ; 3907.43,3164.47 J17.8@3907.43,3114.17 ; 3907.43,3339.45 J17.7@3907.43,3389.76 ; 3957.74,3114.17 J17.8@3907.43,3114.17 ; 3957.74,3389.76 J17.7@3907.43,3389.76 ; 3989.05,3133.69 J17.4@4015.74,3133.69 ; 4015.74,3107.01 J17.4@4015.74,3133.69 ; 4015.74,3160.38 J17.4@4015.74,3133.69 ; 4042.43,3133.69 J17.4@4015.74,3133.69 ; 4073.66,3114.17 J17.5@4123.97,3114.17 ; 4073.66,3389.76 J17.6@4123.97,3389.76 ; 4123.97,3063.86 J17.5@4123.97,3114.17 ; 4123.97,3164.47 J17.5@4123.97,3114.17 ; 4123.97,3339.45 J17.6@4123.97,3389.76 ; 4174.28,3114.17 J17.5@4123.97,3114.17 ; 4174.28,3389.76 J17.6@4123.97,3389.76
  PWR04 w21: 326.66,3696.82 J1.1@353.36,3696.82 ; 353.36,3642.57 J1.1@353.36,3696.82 ; 380.06,3696.82 J1.1@353.36,3696.82 ; J1.2@497.06,3411.32 497.06,3471.47 ; J1.3@705.66,3411.32 705.66,3471.47 ; 712.46,3696.82 J1.5@739.16,3696.82 ; 739.16,3642.57 J1.5@739.16,3696.82 ; 765.87,3696.82 J1.5@739.16,3696.82 ; 1093.39,177.48 J7.4@1131.89,177.48 ; 1131.89,138.98 J7.4@1131.89,177.48 ; 1170.39,177.48 J7.4@1131.89,177.48 ; 1625.39,195.75 J9.5@1625.39,238.19 ; 2075.39,195.75 J9.2@2075.39,238.19 ; J17.6@4123.97,3389.76 4174.28,3389.76
  GND05 w15: 326.66,3696.82 J1.1@353.36,3696.82 ; 353.36,3642.57 J1.1@353.36,3696.82 ; 353.36,3751.07 J1.1@353.36,3696.82 ; 380.06,3696.82 J1.1@353.36,3696.82 ; 414.1,789.42 SS2.1@523.46,789.42 ; 414.1,2600.44 SS1.1@523.46,2600.44 ; 460.53,3411.32 J1.2@497.06,3411.32 ; 497.06,3351.17 J1.2@497.06,3411.32 ; 497.06,3471.47 J1.2@497.06,3411.32 ; 523.46,680.06 SS2.1@523.46,789.42 ; 523.46,898.79 SS2.1@523.46,789.42 ; 523.46,2491.08 SS1.1@523.46,2600.44 ; 523.46,2709.81 SS1.1@523.46,2600.44 ; 533.59,3411.32 J1.2@497.06,3411.32 ; 632.82,789.42 SS2.1@523.46,789.42 ; 632.82,2600.44 SS1.1@523.46,2600.44 ; 669.13,3411.32 J1.3@705.66,3411.32 ; 705.66,3351.17 J1.3@705.66,3411.32 ; 705.66,3471.47 J1.3@705.66,3411.32 ; 706.26,3054.25 J8.2@706.26,3078.97 ; 706.26,3103.69 J8.2@706.26,3078.97 ; 712.46,3696.82 J1.5@739.16,3696.82 ; 730.98,3078.97 J8.2@706.26,3078.97 ; 739.16,3642.57 J1.5@739.16,3696.82 ; 739.16,3751.07 J1.5@739.16,3696.82 ; 742.19,3411.32 J1.3@705.66,3411.32 ; 765.87,3696.82 J1.5@739.16,3696.82 ; 946.39,3142.9 J2.2@974.06,3142.9 ; 974.06,3115.23 J2.2@974.06,3142.9 ; 974.06,3170.57 J2.2@974.06,3142.9 ; 1001.73,3142.9 J2.2@974.06,3142.9 ; 1093.39,177.48 J7.4@1131.89,177.48 ; 1131.89,138.98 J7.4@1131.89,177.48 ; 1131.89,215.98 J7.4@1131.89,177.48 ; 1170.39,177.48 J7.4@1131.89,177.48 ; 1582.95,238.19 J9.5@1625.39,238.19 ; 1625.39,195.75 J9.5@1625.39,238.19 ; 1625.39,280.62 J9.5@1625.39,238.19 ; 1667.83,238.19 J9.5@1625.39,238.19 ; 2032.95,238.19 J9.2@2075.39,238.19 ; 2075.39,195.75 J9.2@2075.39,238.19 ; 2075.39,280.62 J9.2@2075.39,238.19 ; 2117.82,238.19 J9.2@2075.39,238.19 ; 3012.53,789.42 SS3.1@3121.89,789.42 ; 3012.53,2600.44 SS4.1@3121.89,2600.44 ; 3093.19,3255.96 J16.20@3163.19,3255.96 ; 3093.19,3479.56 J16.19@3163.19,3479.56 ; 3121.89,680.06 SS3.1@3121.89,789.42 ; 3121.89,898.79 SS3.1@3121.89,789.42 ; 3121.89,2491.08 SS4.1@3121.89,2600.44 ; 3121.89,2709.81 SS4.1@3121.89,2600.44 ; 3163.19,3185.96 J16.20@3163.19,3255.96 ; 3163.19,3325.96 J16.20@3163.19,3255.96 ; 3163.19,3409.56 J16.19@3163.19,3479.56 ; 3163.19,3549.56 J16.19@3163.19,3479.56 ; 3231.25,789.42 SS3.1@3121.89,789.42 ; 3231.25,2600.44 SS4.1@3121.89,2600.44 ; 3233.19,3255.96 J16.20@3163.19,3255.96 ; 3233.19,3479.56 J16.19@3163.19,3479.56 ; 3255.44,3274.86 J16.13@3284.09,3274.86 ; 3255.44,3400.86 J16.4@3284.09,3400.86 ; 3284.09,3246.2 J16.13@3284.09,3274.86 ; 3284.09,3303.51 J16.13@3284.09,3274.86 ; 3284.09,3372.2 J16.4@3284.09,3400.86 ; 3284.09,3429.51 J16.4@3284.09,3400.86 ; 3312.75,3274.86 J16.13@3284.09,3274.86 ; 3312.75,3400.86 J16.4@3284.09,3400.86 ; 3393.24,3215.76 J16.16@3421.89,3215.76 ; 3393.24,3341.76 J16.7@3421.89,3341.76 ; 3421.89,3244.42 J16.16@3421.89,3215.76 ; 3421.89,3313.1 J16.7@3421.89,3341.76 ; 3421.89,3370.42 J16.7@3421.89,3341.76 ; 3450.55,3215.76 J16.16@3421.89,3215.76 ; 3450.55,3341.76 J16.7@3421.89,3341.76 ; 3610.59,3255.96 J16.21@3680.59,3255.96 ; 3610.59,3479.56 J16.22@3680.59,3479.56 ; 3658.48,785.48 SS6.1@3767.85,785.48 ; 3680.59,3185.96 J16.21@3680.59,3255.96 ; 3680.59,3325.96 J16.21@3680.59,3255.96 ; 3680.59,3409.56 J16.22@3680.59,3479.56 ; 3680.59,3549.56 J16.22@3680.59,3479.56 ; 3750.59,3255.96 J16.21@3680.59,3255.96 ; 3750.59,3479.56 J16.22@3680.59,3479.56 ; 3767.85,676.12 SS6.1@3767.85,785.48 ; 3767.85,894.85 SS6.1@3767.85,785.48 ; 3857.12,3114.17 J17.8@3907.43,3114.17 ; 3857.12,3389.76 J17.7@3907.43,3389.76 ; 3877.21,785.48 SS6.1@3767.85,785.48 ; 3907.43,3063.86 J17.8@3907.43,3114.17 ; 3907.43,3164.47 J17.8@3907.43,3114.17 ; 3907.43,3339.45 J17.7@3907.43,3389.76 ; 3907.43,3440.07 J17.7@3907.43,3389.76 ; 3957.74,3114.17 J17.8@3907.43,3114.17 ; 3957.74,3389.76 J17.7@3907.43,3389.76 ; 3989.05,3133.69 J17.4@4015.74,3133.69 ; 4015.74,3107.01 J17.4@4015.74,3133.69 ; 4015.74,3160.38 J17.4@4015.74,3133.69 ; 4042.43,3133.69 J17.4@4015.74,3133.69 ; 4073.66,3114.17 J17.5@4123.97,3114.17 ; 4073.66,3389.76 J17.6@4123.97,3389.76 ; 4123.97,3063.86 J17.5@4123.97,3114.17 ; 4123.97,3164.47 J17.5@4123.97,3114.17 ; 4123.97,3339.45 J17.6@4123.97,3389.76 ; 4123.97,3440.07 J17.6@4123.97,3389.76 ; 4174.28,3114.17 J17.5@4123.97,3114.17 ; 4174.28,3389.76 J17.6@4123.97,3389.76 ; 4611.24,785.48 SS5.1@4720.61,785.48 ; 4720.61,676.12 SS5.1@4720.61,785.48 ; 4720.61,894.85 SS5.1@4720.61,785.48 ; 4829.97,785.48 SS5.1@4720.61,785.48
  GND05 w30: 4244.76,3179.13 J15.10@4381.49,3179.13
  BOTTOM w6: 332,2533 357,2508 357,2453 ; 338,2541 338,2689 350,2701 ; C24.2@429.68,2179.37 v1(465,2179.37) ; 440,2479 440,2521 433,2528 433,2536.97 412.49,2557.49 412.49,2653.49 489,2730 ; v1(675,814.37) C31.2@700.32,814.37 ; R4.2@965.32,1329.37 1004.68,1290.01 C4.2@1004.68,1289.37 ; 1207,3009.76 1302,3104.76 1302,3169.95 1293.05,3178.9 1238.04,3178.9 1220,3160.86 ; 1424,3068.5 1424,3084.24 ; C55.2@1520.32,1344.37 v1(1520.32,1374.05) ; v1(1724.95,3439.32) 1724.95,3434.42 1834,3325.37 1834,3141.76 ; v1(1855,3114.37) 1860,3119.37 1860,3424.69 C186.2@1855,3429.69 ; C187.2@2065,2589.69 2065,2589.37 2080,2574.37 v1(2085,2574.37) ; 2390,2656.38 2394,2652.38 2394,2597.27 2390,2593.27 2390,2538 2406,2522 2406,1949 2375,1918 2375,1809.37 2312,1746.37 2312,1474.34 2402.97,1383.37 2474,1383.37 v1(2480,1389.37) ; 2544,2891 2574.37,2921.37 2666.5,2921.37 v1(2716,2970.87) 2750.5,3005.37 2806,3005.37 v1(2875,3074.37) ; v1(2590,2969.37) 2640.4,2969.37 2722.4,3051.37 2762.68,3051.37 2805,3093.69 ; 2874,2614.37 2810,2614.37 2790,2594.37 2790,2509.37 2768,2487.37 2577,2487.37 2565,2475.37 2565,1829.37 2618,1776.37 3728,1776.37 v1(3805,1699.37) v1(3910,1594.37) v1(3910,1494.37) ; v1(2970,1969.37) 2990.35,1949.02 3054.65,1949.02 3075,1969.37 ; 3095.01,3154.36 3175.01,3154.36 v1(3195,3134.37) 3267.98,3061.39 3267.98,3028.75 3271.68,3025.06 3271.68,2896.05 3260,2884.37 3230,2884.37 v1(3205,2909.37) ; v1(3155,2029.37) 3200,2029.37 3215,2014.37 3215,1996.37 v1(3219,1992.37) ; 3669,2271 3748.37,2271 v1(3765,2254.37) ; 3814,3060 3814,2848 3926,2736 ; 3877,2704 3877,2422.37 v1(3885,2414.37) ; v1(3910,2899.37) 3910,2872.81 3998.61,2784.21 v1(4047.39,2784.21) ; v1(4185,2034.37) 4085.8,2133.57 3597.33,2133.57 3571,2107.24 3571,2083.37 3590,2064.37 v1(3590,2049.37) 3603.13,2049.37 3622.13,2068.37 3816,2068.37 3844,2096.37 4052.11,2096.37 4166.51,1981.97 4333.49,1981.97 4365,2013.48 v1(4365,2034.37) ; 4349.5,2951.5 4349.5,2970.5 ; 4452,2723 4452,2965.7 4488.17,3001.87 ; v1(4486.2,2323.17) 4486.2,2293.17 4500,2279.37 4565,2279.37 4590.78,2253.59 4627.87,2253.59 4640,2241.46 4640,2059.77 v1(4640.4,2059.37) 4625,2059.37 4440.2,1874.57 4119.91,1874.57 4050.11,1944.37 v1(4025,1944.37) 4025,1924.37 4050,1899.37 4050,1879.37 v1(4087.5,1841.87) 4090,1839.37 4480.11,1839.37 4680,2039.26 v1(4680,2099.37) v1(4680,2234.37)
  BOTTOM w7: U33.29@1920,2414.37 U33.4@1998.74,2414.37
  BOTTOM w8: v1(1538.31,2925.22) 1565,2898.52 1565,2769.37 ; v1(1745,2184.37) 1762.28,2184.37 v1(1873.64,2295.73) 1884.57,2306.66 U33.13@1884.57,2335.63 1884.57,2378.94 v1(1895,2389.37) ; v1(1805,2414.37) U33.18@1841.26,2414.37 1889,2414.37 1895,2420.37 v1(1895,2439.37) ; v1(1865,2664.37) 1905,2704.37 1965.32,2704.37 C188.2@1985.32,2724.37 ; v1(1865,2864.37) Z11.1@1895.32,2864.37 ; Z8.1@2024.68,2864.37 2024.68,2882.1 v1(2013.92,2892.86) 2013.92,2923.29 2053,2962.37 2097,2962.37 2105,2970.37 2105,3099.37 v1(2090,3114.37) ; v1(4480,964.37) 4485,959.37 U32.2@4518.43,959.37 ; J23.4@4978.61,659.45 v1(5025,659.45)
  BOTTOM w10: v1(105,1774.37) 125,1774.37 135,1784.37 R7.2@135,1809.69 ; v1(105,1929.05) C18.1@135,1929.05 R9.2@175,1929.05 ; v1(290,474.37) R40.2@320.32,474.37 ; v1(420,474.37) R41.2@450.32,474.37 ; v1(540,474.37) R42.2@580.32,474.37 ; v1(1305,1009.37) 1260,1054.37 1260,1314.37 1349,1403.37 1349,1523.37 v1(1380,1554.37) 1410,1584.37 1607.8,1584.37 1620,1596.57 1620,1684.37 1622.2,1686.57 1622.2,1686.7 1635.67,1700.17 1635.8,1700.17 1640,1704.37 1689.47,1704.37 ; v1(1435,3483.76) U37.8@1435,3512.15 U37.3@1435,3546.59 v1(1435,3579.37) ; D10.1@1540,1224.92 1540,1234.37 1470,1304.37 1470,1494.37 v1(1520,1494.37) v1(1658,1494.37) 1665,1494.37 1745.2,1574.57 ; J9.5@1625.39,238.19 1625.39,215.41 1599.35,189.37 1440,189.37 1424,205.37 1424,303.37 1465,344.37 v1(1465,764.37) 1460,769.37 1460,1094.37 1450,1104.37 v1(1304,1104.37) 1294,1114.37 1294,1293.37 1384,1383.37 1384,1488.63 1439.74,1544.37 1650,1544.37 v1(1660,1554.37) 1670,1564.37 1670,1684.9 1689.47,1704.37 ; v1(1760,3139.37) Z10.1@1760,3169.69 ; 1770,609.37 1770,440.5 1878.96,331.54 1878.96,210.41 1905,184.37 2021.57,184.37 J9.2@2075.39,238.19 2075.39,348.98 1821,603.37 ; Z9.1@1775,3469.05 v1(1775,3499.37) ; C53.2@1845,1514.05 1824.68,1534.37 1785.4,1534.37 1745.2,1574.57 ; C186.2@1855,3429.69 1881.48,3429.69 v1(1881.8,3429.37) ; v1(1865,2764.37) R218.2@1895.32,2764.37 ; v1(2420,1709.37) 2490,1779.37 2490,2565 2480,2575 ; v1(2685,3469.37) 2700,3469.37 2722.5,3491.87 Q10.2@2722.5,3510.87 ; 2739,2803.37 2895.43,2959.8 2909.93,2959.8 v1(2910.5,2960.37) 2910.5,2968.67 2935.2,2993.37 3006.63,2993.37 3077,3063.74 3077,3136.35 3095.01,3154.36 ; v1(3115,1584.37) 3115,1694.37 3131,1710.37 3174,1710.37 v1(3195,1689.37) 3215,1709.37 R73.2@3225.32,1709.37 ; R176.2@3200.32,2939.37 3200.32,2914.05 v1(3205,2909.37) ; v1(3305,3164.37) 3325,3144.37 v1(3325,3124.37) U17.3@3325,3091.59 U17.8@3325,3057.15 ; U16.8@3500,3057.15 U16.3@3500,3091.59 3500,3123.37 v1(3502,3125.37) ; v1(3765,2254.37) 3770,2259.37 U18.3@3797.78,2259.37 U18.8@3832.22,2259.37 3865,2259.37 3870,2254.37 v1(3870,2254.64) ; v1(3910,1494.37) 3930,1474.37 v1(3930,1229.37) v1(3930,1109.37) v1(3930,1009.37) ; v1(3910,2899.37) 3910,2964.37 3930,2984.37 3994.58,2984.37 v1(4025,2953.95) ; v1(4045,769.37) v1(4090,769.37) ; v1(4193.45,2332.17) 4195,2333.72 C75.2@4195,2354.69 4158.93,2354.69 Y2.2@4144.53,2369.09 4144.53,2365.9 4110.13,2331.5 4060.82,2331.5 4047.25,2345.07 v1(4047.25,2414.37) v1(4047.25,2459.65) Y2.4@4085.47,2459.65 4085.47,2461.42 4120.29,2496.24 4172.81,2496.24 C74.2@4195,2474.05 4209.68,2459.37 v1(4225,2459.37) ; v1(4585,2584.37) 4595,2574.37 C78.2@4595,2554.05 ; v1(4935,2644.37) 4951.64,2627.73 J19.16@4980.62,2627.73 5031.64,2627.73 v1(5035,2624.37) ; J21.18@4978.61,1801.18 5009,1801.18 5019,1811.18 5019,1818.37 v1(5025,1824.37) ; J19.28@4980.62,2391.51 v1(5035,2391.51) ; J19.25@4980.62,2450.57 v1(5035,2450.57) ; J19.22@4980.62,2509.62 v1(5035,2509.62) ; J19.19@4980.62,2568.68 v1(5035,2568.68) ; v1(5090,2139.37) v1@5090.32,2139.05 ; 1689.47,1704.37 1740.2,1704.37 v1(1745.2,1709.37) U9.15@1745.2,1649.17 1745.2,1574.57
